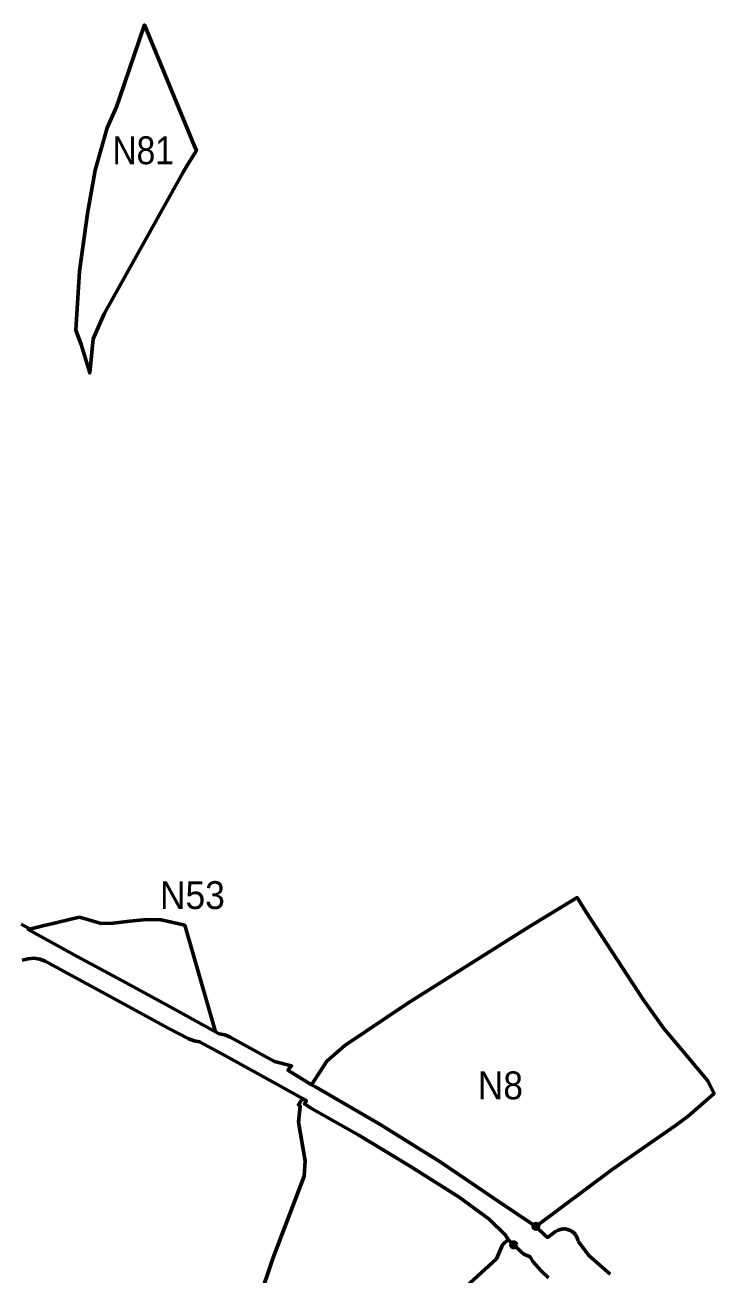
# Model space of a CAD drawing. Extents: x -650277 to -643422, y -1073980 to -1066720.
# Drawn here: x -646020 to -645426, y -1069207 to -1068130 of the extents above; entities that cross this region are included whole.
import ezdxf

# ---------------------------------------------------------------- set-up
doc = ezdxf.new("R2010")
doc.units = 0
doc.header["$LTSCALE"] = 9.6
doc.header["$PDMODE"] = 32
doc.header["$PDSIZE"] = 4.8
for name, color, linetype, lineweight in [('42', 7, 'Continuous', 60), ('48', 7, 'Continuous', 60), ('60', 7, 'Continuous', 60), ('63', 7, 'Continuous', 25), ('7', 7, 'Continuous', 60)]:
    doc.layers.add(name, color=color, linetype=linetype, lineweight=lineweight)

msp = doc.modelspace()

# ---------------------------------------------------------------- linework, layer by layer
at = {"layer": '42'}
for points in [[(-646017.55, -1068909.75), (-646010.48, -1068907.86), (-646004.88, -1068906.5), (-645994.9, -1068904.1), (-645980.93, -1068900.85), (-645973.36, -1068898.93)], [(-645973.36, -1068898.93), (-645954.59, -1068904.41), (-645944.23, -1068904.13), (-645930.1, -1068902.47), (-645915.61, -1068901.02), (-645902.91, -1068901.43), (-645882.63, -1068905.88), (-645856.26, -1068997.79)], [(-645856.26, -1068997.79), (-645892.77, -1068977.86), (-645933.28, -1068955.74), (-645975.31, -1068932.8), (-646017.55, -1068909.75)]]:
    msp.add_lwpolyline(points, dxfattribs=at)
at = {"layer": '48'}
msp.add_lwpolyline([(-645874.15, -1068234.44), (-645917.44, -1068129.99), (-645938.87, -1068193.06), (-645941.41, -1068200.54), (-645949.52, -1068218.72), (-645959.76, -1068255.23), (-645966.56, -1068292.38), (-645973.25, -1068342.08), (-645976.63, -1068393.14), (-645971.94, -1068405.38), (-645964.53, -1068429.83), (-645963.12, -1068415.21), (-645961.7, -1068400.54), (-645952.21, -1068378.95), (-645926.06, -1068332.18), (-645883.87, -1068256.88), (-645880.28, -1068250.47), (-645872.64, -1068238.08)], close=True, dxfattribs=at)
at = {"layer": '60'}
for points in [[(-645579.94, -1069165.52), (-645616.63, -1069140.8), (-645662.44, -1069109.89), (-645713.61, -1069078.06), (-645770.04, -1069045.34), (-645773.38, -1069043.46), (-645793.638, -1069031.021), (-645790.53, -1069027.19), (-645805.16, -1069023.52), (-645843.56, -1069002.41), (-645848.18, -1069000.48), (-645852.91, -1068999.62), (-645856.26, -1068997.79), (-645892.77, -1068977.86), (-645933.28, -1068955.74), (-645975.31, -1068932.8), (-646017.55, -1068909.75), (-646017.39, -1068908.42), (-646023.56, -1068905.05)], [(-646022.77, -1068936.12), (-646017.6, -1068934.89), (-646012.64, -1068934.34), (-646007.7, -1068935.18), (-646002.95, -1068936.95), (-645993.5, -1068942.1), (-645940.77, -1068970.74), (-645896.91, -1068994.75), (-645879.17, -1069004.02), (-645874.49, -1069005.73), (-645869.83, -1069006.45), (-645850.79, -1069016.84), (-645803.29, -1069042.92), (-645781.12, -1069055.29), (-645777.73, -1069057.2), (-645779.49, -1069059.92), (-645773.29, -1069063.99), (-645732.65, -1069086.82), (-645688.87, -1069113.44), (-645646.08, -1069140.37), (-645620.2, -1069159.26), (-645606.11, -1069172.98), (-645603.91, -1069176.86), (-645599, -1069181.48)], [(-645571.9, -1069173.43), (-645579.94, -1069165.52), (-645579.94, -1069165.52)], [(-645543.43, -1069178.39), (-645543.547, -1069177.727), (-645543.706, -1069177.053), (-645543.907, -1069176.37), (-645544.154, -1069175.682), (-645544.448, -1069174.993), (-645544.792, -1069174.308), (-645545.186, -1069173.63), (-645545.631, -1069172.966), (-645546.127, -1069172.32), (-645546.674, -1069171.699), (-645547.269, -1069171.107), (-645547.91, -1069170.551), (-645548.594, -1069170.034), (-645549.317, -1069169.563), (-645550.076, -1069169.141), (-645550.863, -1069168.772), (-645551.674, -1069168.459), (-645552.504, -1069168.203), (-645553.344, -1069168.007), (-645554.191, -1069167.87), (-645555.036, -1069167.793), (-645555.875, -1069167.772), (-645556.702, -1069167.808), (-645557.511, -1069167.896), (-645558.298, -1069168.035), (-645559.06, -1069168.219), (-645559.793, -1069168.445), (-645560.494, -1069168.709), (-645561.162, -1069169.007), (-645561.794, -1069169.334), (-645562.39, -1069169.686), (-645562.95, -1069170.06), (-645567.5, -1069173.46), (-645569.81, -1069175.03), (-645571.9, -1069173.43)], [(-645515.89, -1069206.66), (-645534.25, -1069190.56), (-645543.43, -1069178.39)], [(-645599, -1069181.48), (-645599, -1069181.48), (-645592.24, -1069187.73), (-645590.41, -1069189.45), (-645584.73, -1069191.88), (-645582.63, -1069195.88), (-645575.58, -1069203.57), (-645568.9, -1069209.87)]]:
    msp.add_lwpolyline(points, dxfattribs=at)
for p in [(-645579.94, -1069165.52), (-645599, -1069181.48)]:
    msp.add_point(p, dxfattribs=at)
at = {"layer": '7'}
msp.add_lwpolyline([(-645770.04, -1069045.34), (-645713.61, -1069078.06), (-645694.447, -1069089.98), (-645662.44, -1069109.89), (-645616.63, -1069140.8), (-645579.94, -1069165.52), (-645514.08, -1069116.5), (-645459.5, -1069078.59), (-645448.49, -1069070.45), (-645426.3, -1069051.02), (-645431.85, -1069039.83), (-645449.72, -1069018.58), (-645469.5, -1068995.09), (-645487.38, -1068969.87), (-645536.63, -1068894.79), (-645544.33, -1068882.17), (-645586.28, -1068907.71), (-645690.34, -1068973.16), (-645744.65, -1069009.71), (-645760.07, -1069023.11), (-645773.38, -1069043.46)], close=True, dxfattribs=at)
msp.add_lwpolyline([(-645643.34, -1069220.59), (-645613.9, -1069193.45), (-645608.71, -1069181.51), (-645603.91, -1069176.86), (-645606.11, -1069172.98), (-645620.2, -1069159.26), (-645646.08, -1069140.37), (-645688.87, -1069113.44), (-645732.65, -1069086.82), (-645773.29, -1069063.99), (-645779.49, -1069059.92), (-645777.73, -1069057.2), (-645781.12, -1069055.29), (-645784.69, -1069060.74), (-645783.02, -1069061.84), (-645784.52, -1069075.66), (-645778.75, -1069108.98), (-645779.685, -1069122.296), (-645806.806, -1069193.112), (-645840.644, -1069294.052)], dxfattribs=at)

# ---------------------------------------------------------------- texts
at = {"layer": '63'}
for s, width, p in [('N81', 0.9, (-645945, -1068250)), ('N53', 0.95, (-645904, -1068892)), ('N8', 0.95, (-645630, -1069056))]:
    msp.add_text(s, height=24, dxfattribs=dict(at, width=width)).set_placement(p)

doc.saveas('drawing.dxf')
